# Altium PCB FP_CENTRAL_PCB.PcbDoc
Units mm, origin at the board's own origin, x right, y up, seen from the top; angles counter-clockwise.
Board outline 52.92 x 50.17 mm, 2 copper layers (Top Layer, Bottom Layer), stack 1.671 mm thick; 8 components, 14 nets, 36 pads, 5 vias.
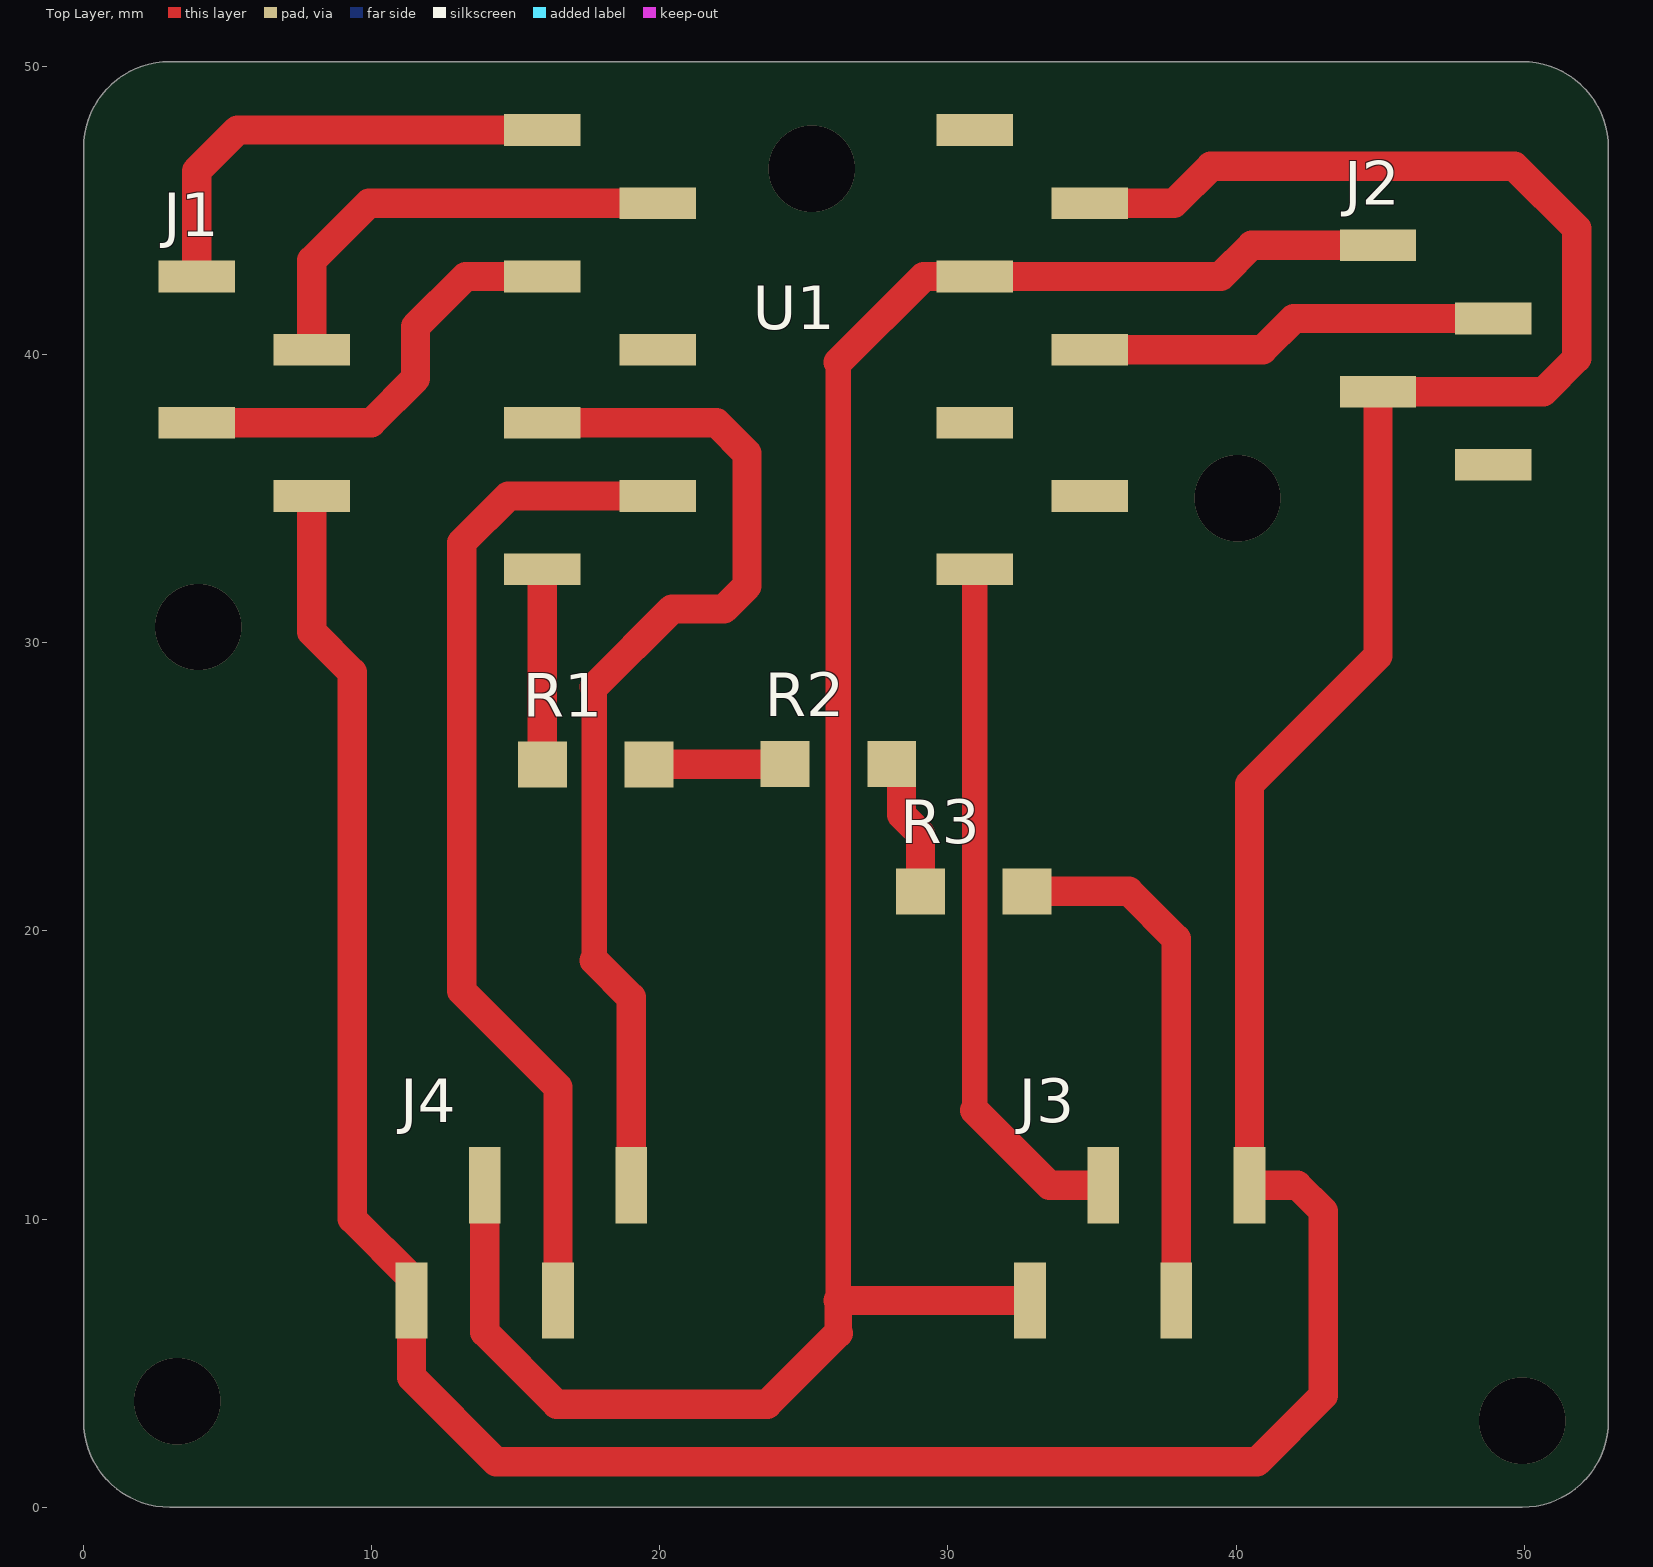
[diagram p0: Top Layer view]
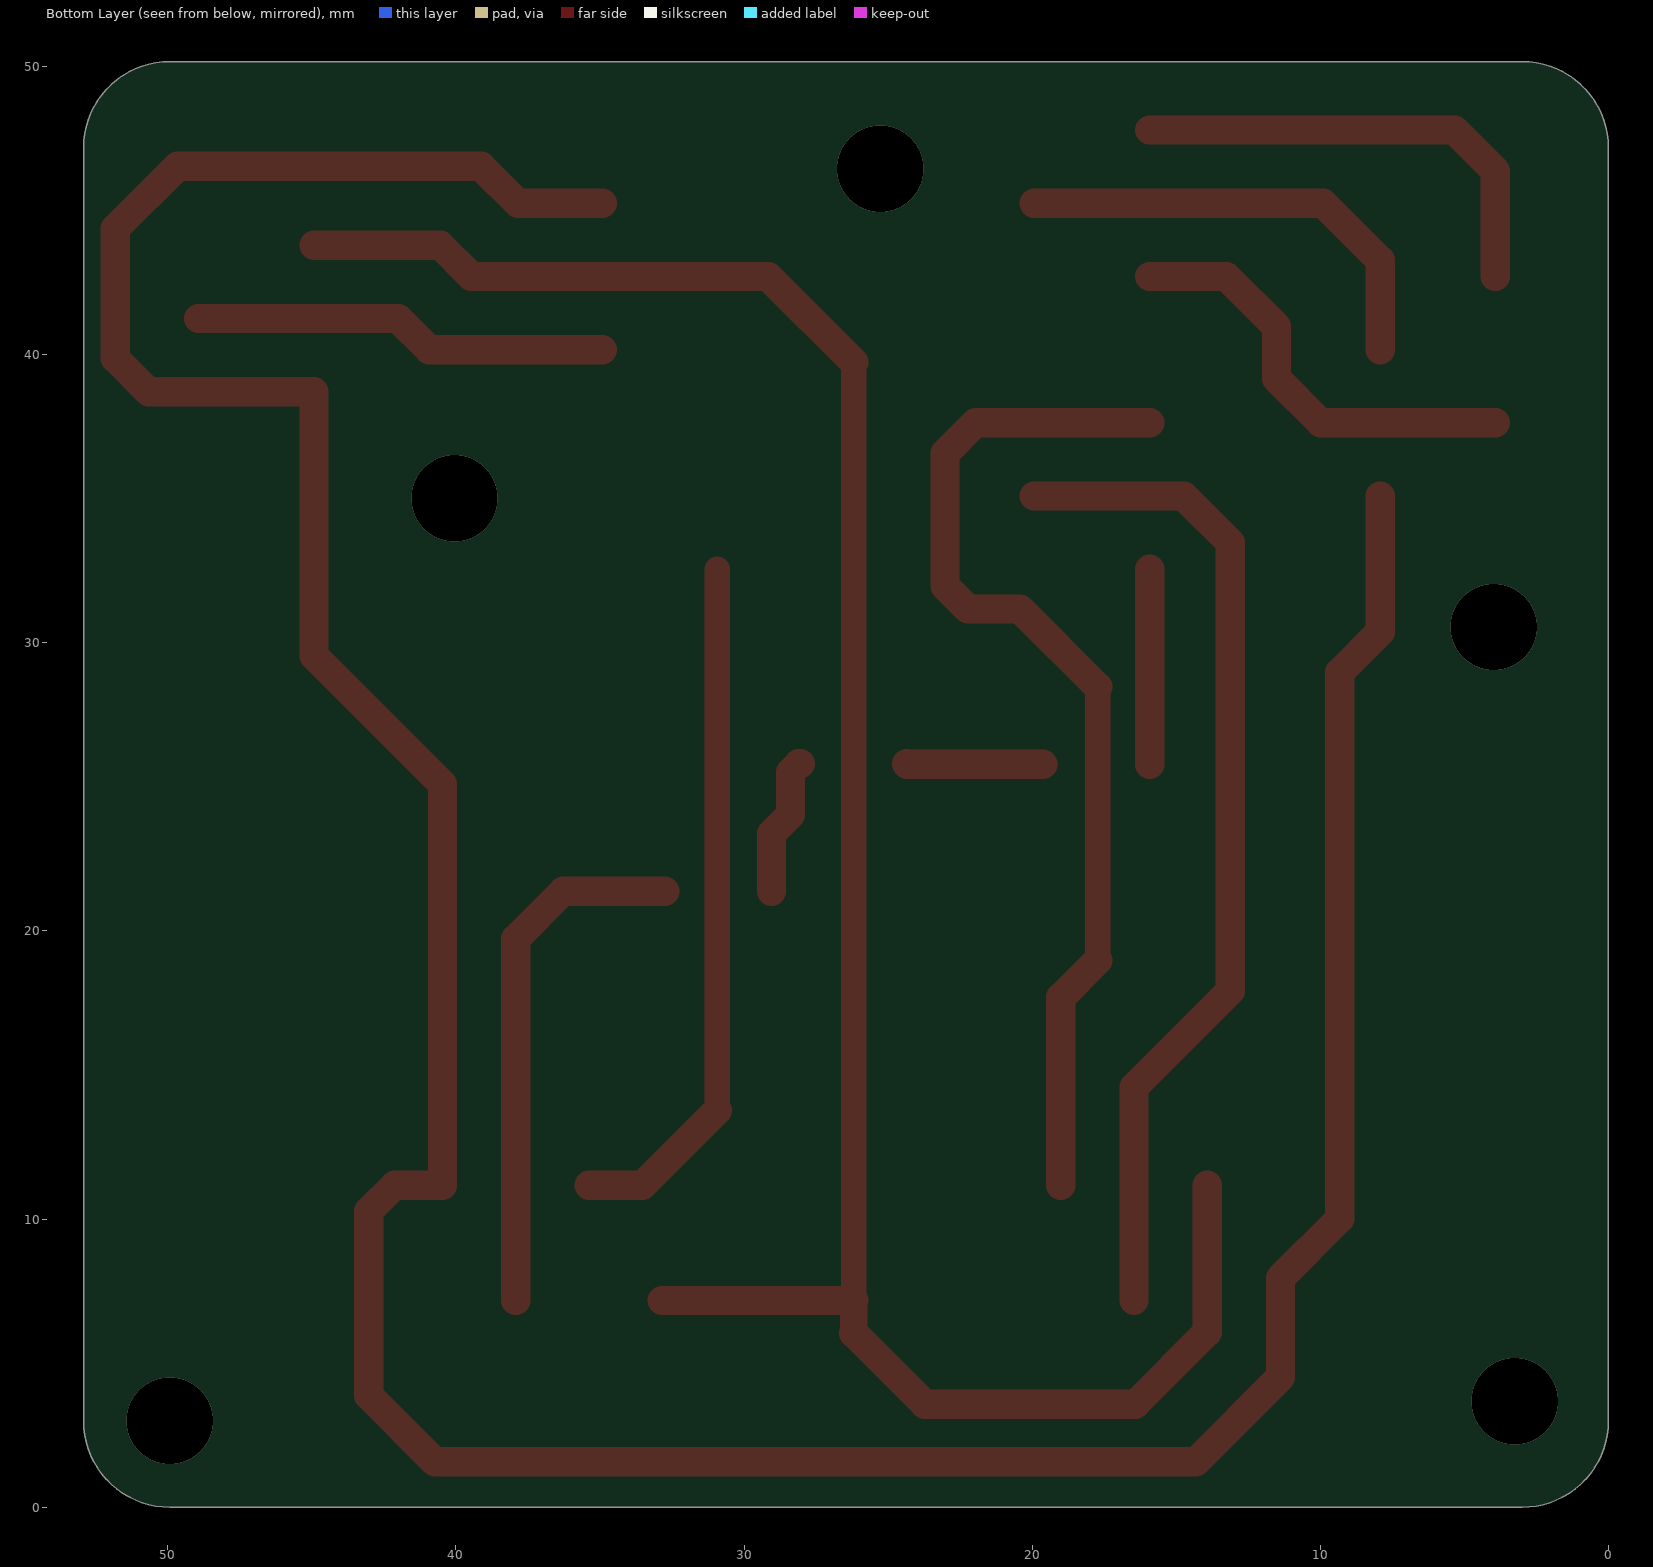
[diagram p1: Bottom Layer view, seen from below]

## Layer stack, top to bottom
Top Solder: solder mask 0.0102, Solder Resist, Dk 3.5
Top Layer: signal copper 0.0356
Dielectric 1: dielectric 1.6, FR-4, Dk 4.8
Bottom Layer: signal copper 0.0356
Bottom Solder: solder mask 0.0102, Solder Resist, Dk 3.5

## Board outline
3,0 cw(c3,3) 0,3 0,47.175 cw(c3,47.175) 3,50.175 49.925,50.175 cw(c49.925,47.175) 52.925,47.175 52.925,3 cw(c49.925,3) 49.925,0

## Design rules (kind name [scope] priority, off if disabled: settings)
Clearance [All] p1: gap=0.254 ignorepadtopadclearanceinfootprint=FALSE
PolygonConnect [All] p1: connectstyle=Relief reliefconductorwidth=0.254 reliefentries=4 polygonreliefangle="90 Angle" airgapwidth=0.254
RoutingVias [All] p1: holewidth=0.711 width=1.27 viastyle="Through Hole" minholewidth=0.711 minwidth=1.27 maxholewidth=0.711 maxwidth=1.27
SolderMaskExpansion [All] p1: expansion=0.102 istentingtop=FALSE
SupplyNets "Schematic Supply Nets_2" [InNet('GND')] p1: voltage=0.000
SupplyNets "Schematic Supply Nets_1" [InNet('5V')] p2: voltage=0.000
SupplyNets "Schematic Supply Nets" [InNet('3V3')] p3: voltage=0.000
Width [All] p1: maxlimit=1.27 minlimit=0.254 preferedwidth=1.016 minimp=50.000000 maximp=50.000000 favimp=50.000000
30 further rules are at their usual default settings.

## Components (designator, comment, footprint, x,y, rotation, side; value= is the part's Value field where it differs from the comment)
J1 "Header 1x4" HDR4X1_FEMALE 3.925,42.716 r0 top
J2 "Header 1x4" HDR4X1_FEMALE 44.925,43.796 r0 top
J3 "Header 1x4" HDR4X1_FEMALE 32.845,7.176 r90 top
J4 "Header 1x4" HDR4X1_FEMALE 11.385,7.176 r90 top
R1 "R499" RES1206 15.925,25.776 r0 top
R2 "R499" RES1206 24.35,25.801 r0 top
R3 "R499" RES1206 29.05,21.376 r0 top
U1 "XIAO ESP32 S3" XIAO_ESP32_S3_SHIELD 17.925,40.176 r0 top

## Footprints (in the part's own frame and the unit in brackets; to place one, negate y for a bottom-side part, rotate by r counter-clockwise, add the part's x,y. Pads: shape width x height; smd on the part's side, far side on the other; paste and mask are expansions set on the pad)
HDR4X1_FEMALE [mm]
  rect 2.65x1.1 smd: 1(0,0) 2(4,-2.54) 3(0,-5.08) 4(4,-7.62)
  body extent -0.76,-7.7 4.74,0.34, height 2.33
RES1206 [mm]
  rect 1.7x1.6 smd: 1(0,0) 2(3.7,0)
  body extent 0.25,-0.79 3.35,0.81, height 0.55
XIAO_ESP32_S3_SHIELD [mm]
  rect 2.65x1.1 smd: 1(-2,7.62) 2(2,5.08) 3(-2,2.54) 4(2,0) 5(-2,-2.54) 6(2,-5.08) 7(-2,-7.62) 8(13,-7.62) 9(17,-5.08) 10(13,-2.54) 11(17,0) 12(13,2.54) 13(17,5.08) 14(13,7.62)
  body extent -2.76,-10.77 17.74,11.71, height 7.21

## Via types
v1: diameter 3, hole 3, Top Layer to Bottom Layer, 5 vias

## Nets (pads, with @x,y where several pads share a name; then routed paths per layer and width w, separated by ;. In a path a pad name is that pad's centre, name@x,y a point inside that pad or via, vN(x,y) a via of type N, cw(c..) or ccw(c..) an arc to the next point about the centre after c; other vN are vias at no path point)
3V3: J2.1 J3.1 J4.2 U1.12 | length 80.2
  Top Layer w0.889: 26.191,7.176 26.191,39.742
  Top Layer w0.965: 26.191,6.042 26.191,7.176
  Top Layer w1.016: J4.2 13.925,6.076 16.425,3.576 23.725,3.576 26.191,6.042 ; 26.191,7.176 J3.1 ; 26.191,39.742 29.165,42.716 U1.12 39.465,42.716 40.545,43.796 J2.1
5V: U1.14
D4/SDA: J4.4 U1.5 | length 37.2
  Top Layer w0.889: 17.725,18.976 17.725,28.476
  Top Layer w1.016: U1.5 21.965,37.636 23.025,36.576 23.025,31.976 22.225,31.176 20.425,31.176 17.725,28.476 ; 17.725,18.976 19.005,17.696 J4.4 J4.4@19.005,11.667
D5/SCL: J4.3 U1.6 | length 35.2
  Top Layer w1.016: J4.3 16.465,14.576 13.125,17.916 13.125,33.476 14.745,35.096 U1.6
GND: J1.4 J2.3 J3.4 J4.1 U1.13 | length 134.7
  Top Layer w1.016: J1.4 7.925,30.376 9.325,28.976 9.325,10.011 11.385,7.951 J4.1 11.385,4.516 14.325,1.576 40.725,1.576 43.025,3.876 43.025,10.276 42.125,11.176 J3.4 40.465,25.09 44.925,29.55 J2.3 50.665,38.716 51.825,39.876 51.825,44.376 49.665,46.536 39.125,46.536 37.845,45.256 U1.13
NetJ1_1: J1.1 U1.1 | length 16.2
  Top Layer w1.016: J1.1 3.925,46.376 5.345,47.796 U1.1
NetJ1_2: J1.2 U1.2 | length 15.9
  Top Layer w1.016: J1.2 7.925,43.276 9.905,45.256 U1.2
NetJ1_3: J1.3 U1.3 | length 15.2
  Top Layer w1.016: J1.3 9.985,37.636 11.525,39.176 11.525,40.976 13.265,42.716 U1.3
NetJ2_2: J2.2 U1.11 | length 14.4
  Top Layer w1.016: U1.11 40.925,40.176 42.005,41.256 J2.2
NetJ3_2: J3.2 U1.8 | length 24.3
  Top Layer w0.889: 30.925,13.776 U1.8
  Top Layer w1.016: 30.925,13.776 33.525,11.176 J3.2
NetJ3_3: J3.3 R3.2 | length 18.4
  Top Layer w1.016: R3.2 36.275,21.376 37.925,19.726 J3.3
NetR1_1: R1.1 U1.7 | length 6.8
  Top Layer w1.016: R1.1 U1.7
NetR1_2: R1.2 R2.1 | length 4.7
  Top Layer w1.016: R1.2 19.638,25.789 24.338,25.789 R2.1
NetR2_2: R2.2 R3.1 | length 4.9
  Top Layer w1.016: R2.2 28.1,25.801 28.392,25.509 28.392,24.034 29.05,23.376 R3.1
pads on no net: J2.4 U1.4 U1.9 U1.10
copper on no net:
  other v1: 49.925,3 3.25,3.675 3.975,30.55 40.05,35.025 25.275,46.45

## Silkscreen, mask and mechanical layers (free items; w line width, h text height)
Mechanical 1:
  the board outline again, w0.254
